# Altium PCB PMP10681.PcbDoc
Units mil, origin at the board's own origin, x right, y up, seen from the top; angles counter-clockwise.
Board outline 3500 x 2650 mil, 4 copper layers (Top Layer, MidLayer1, MidLayer2, Bottom Layer), stack 62.2 mil thick; 65 components, 23 nets, 138 pads, 219 vias.
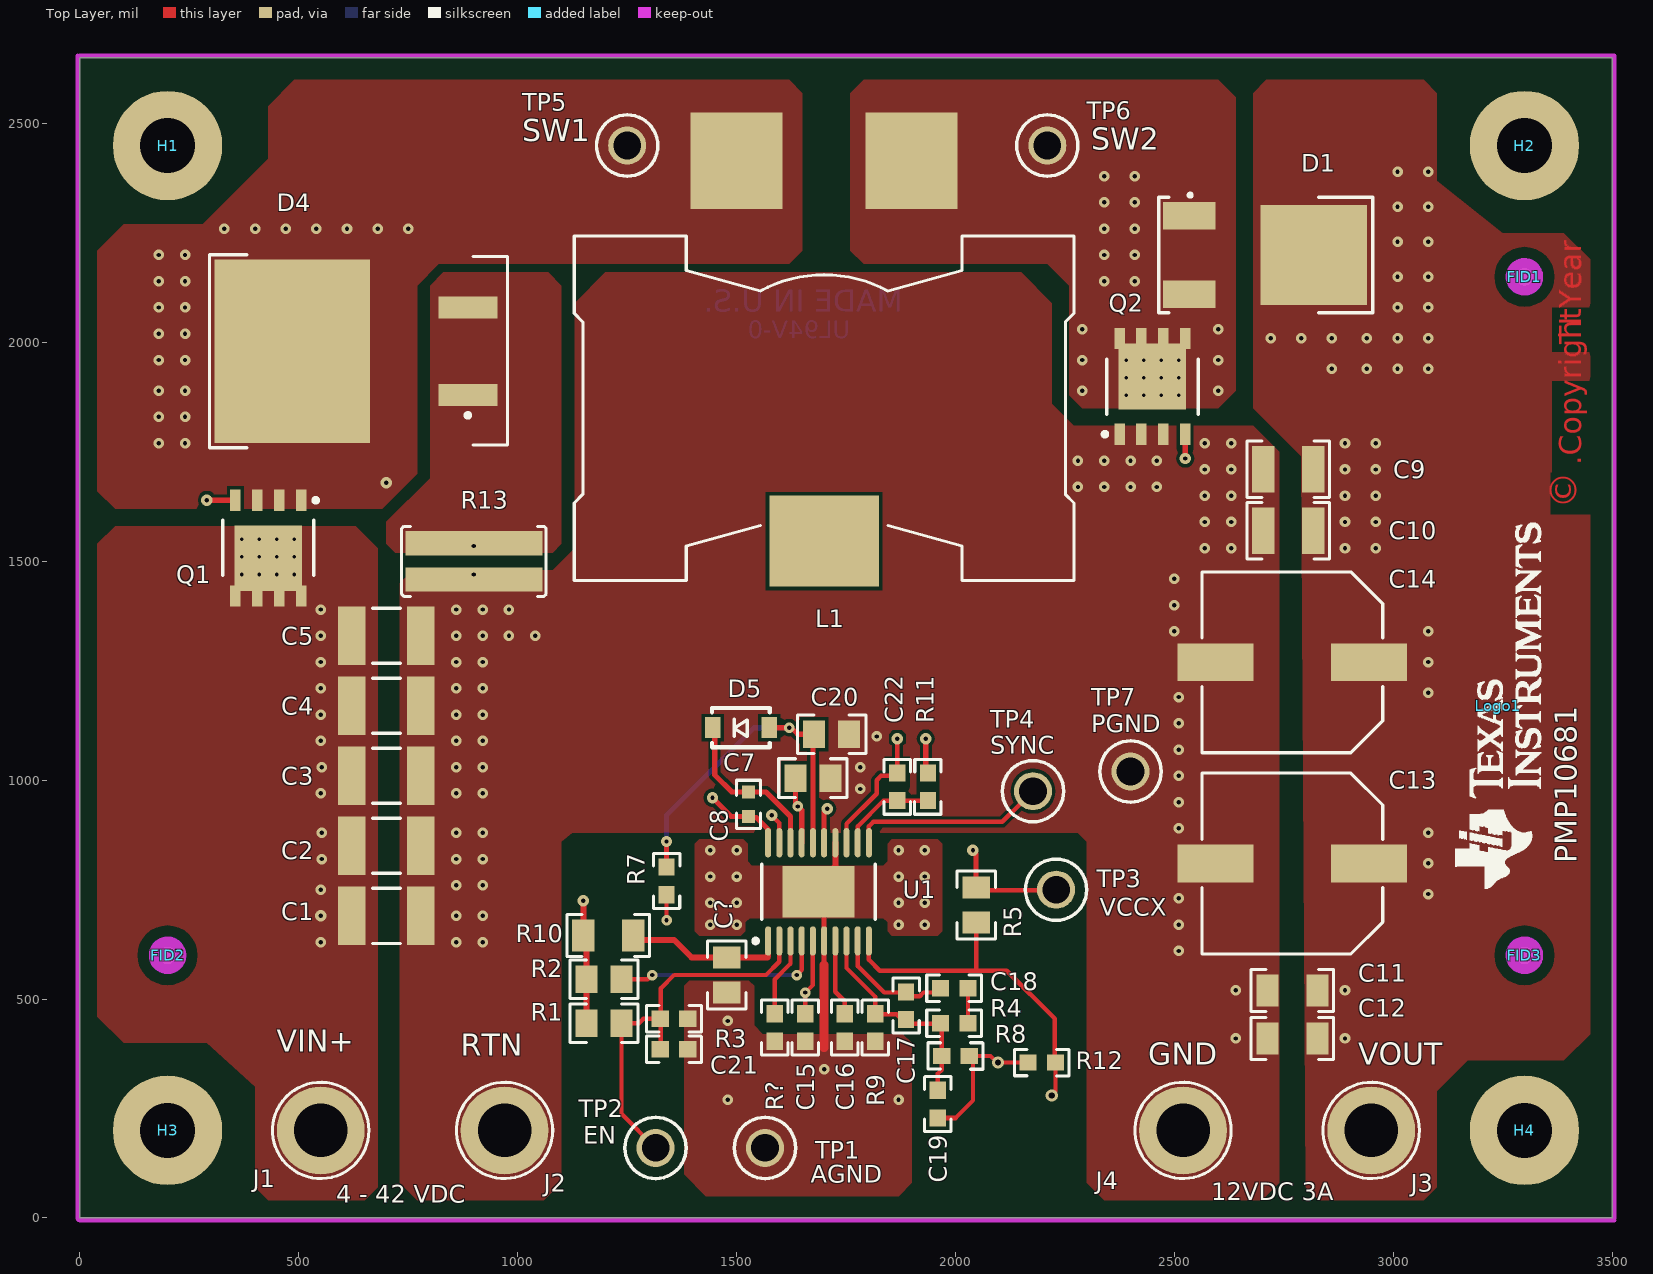
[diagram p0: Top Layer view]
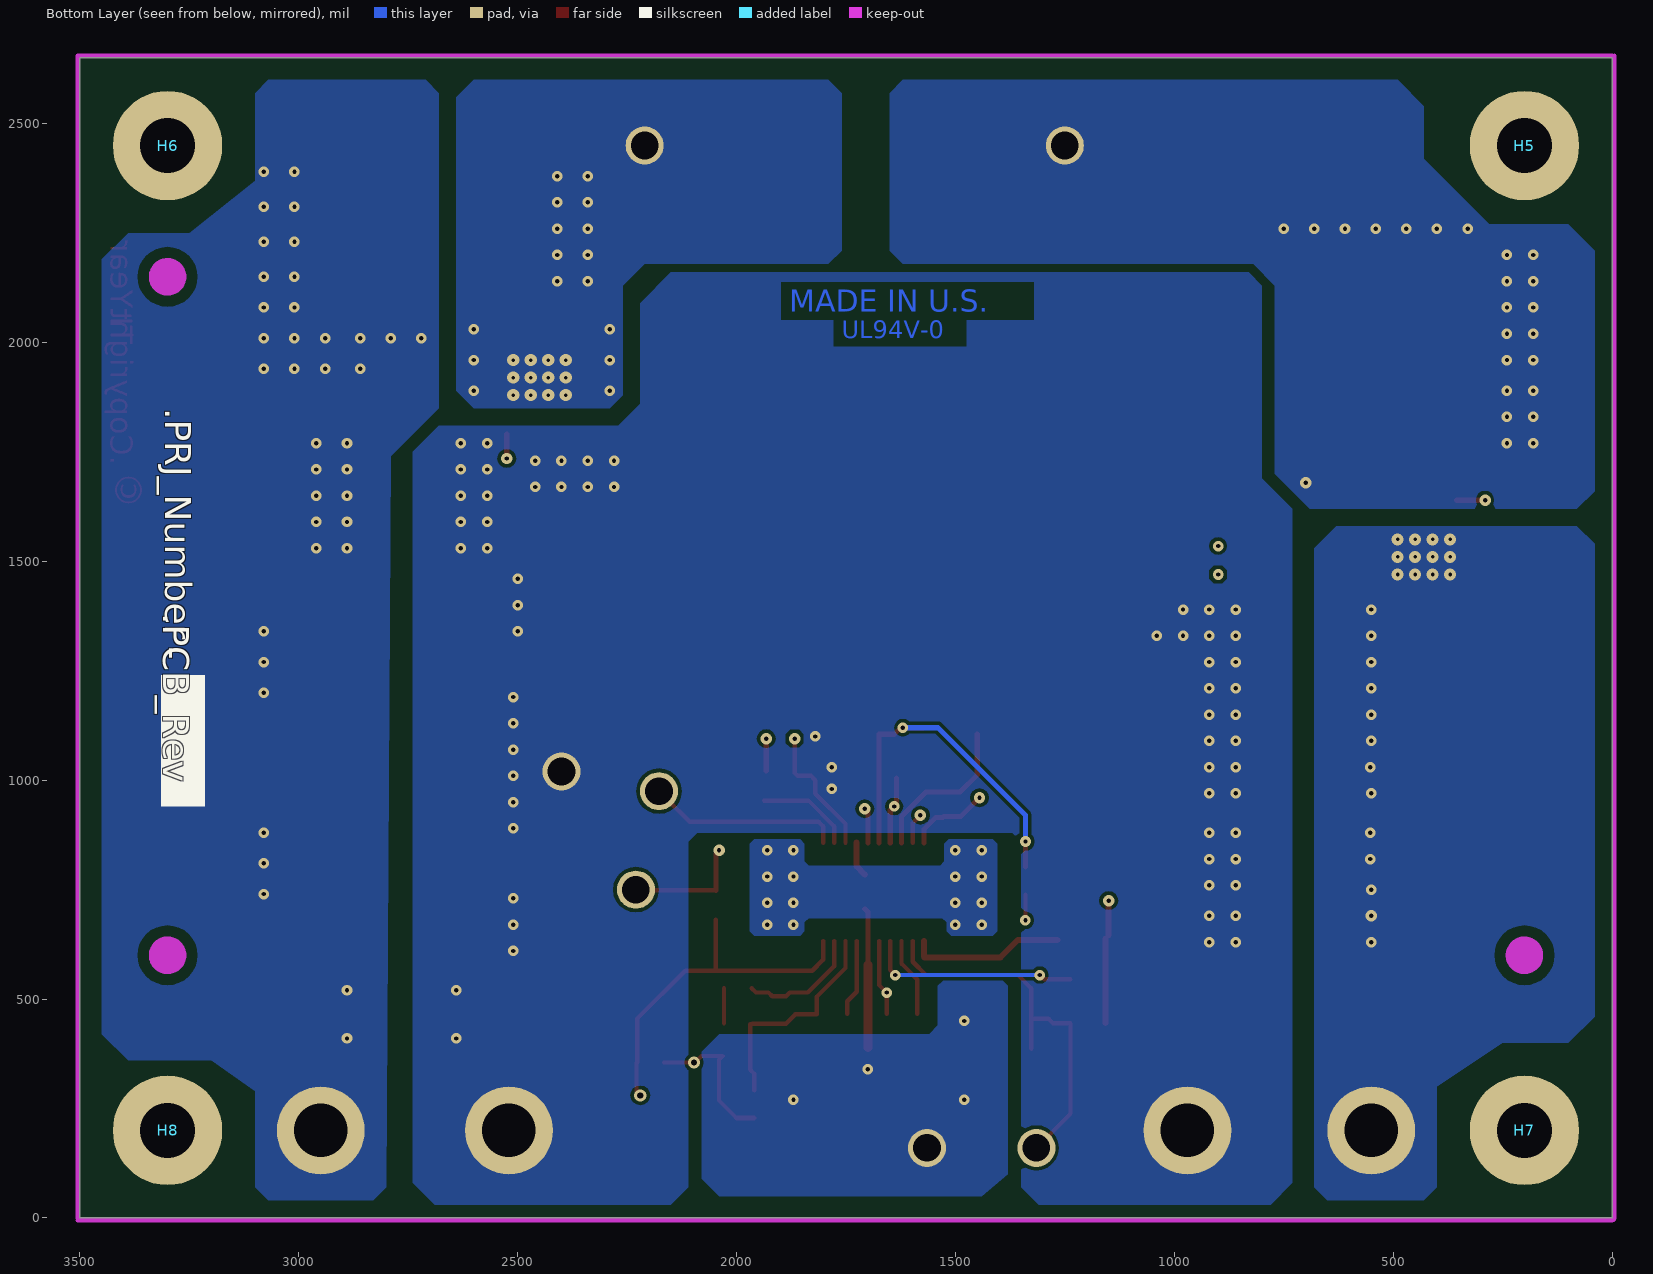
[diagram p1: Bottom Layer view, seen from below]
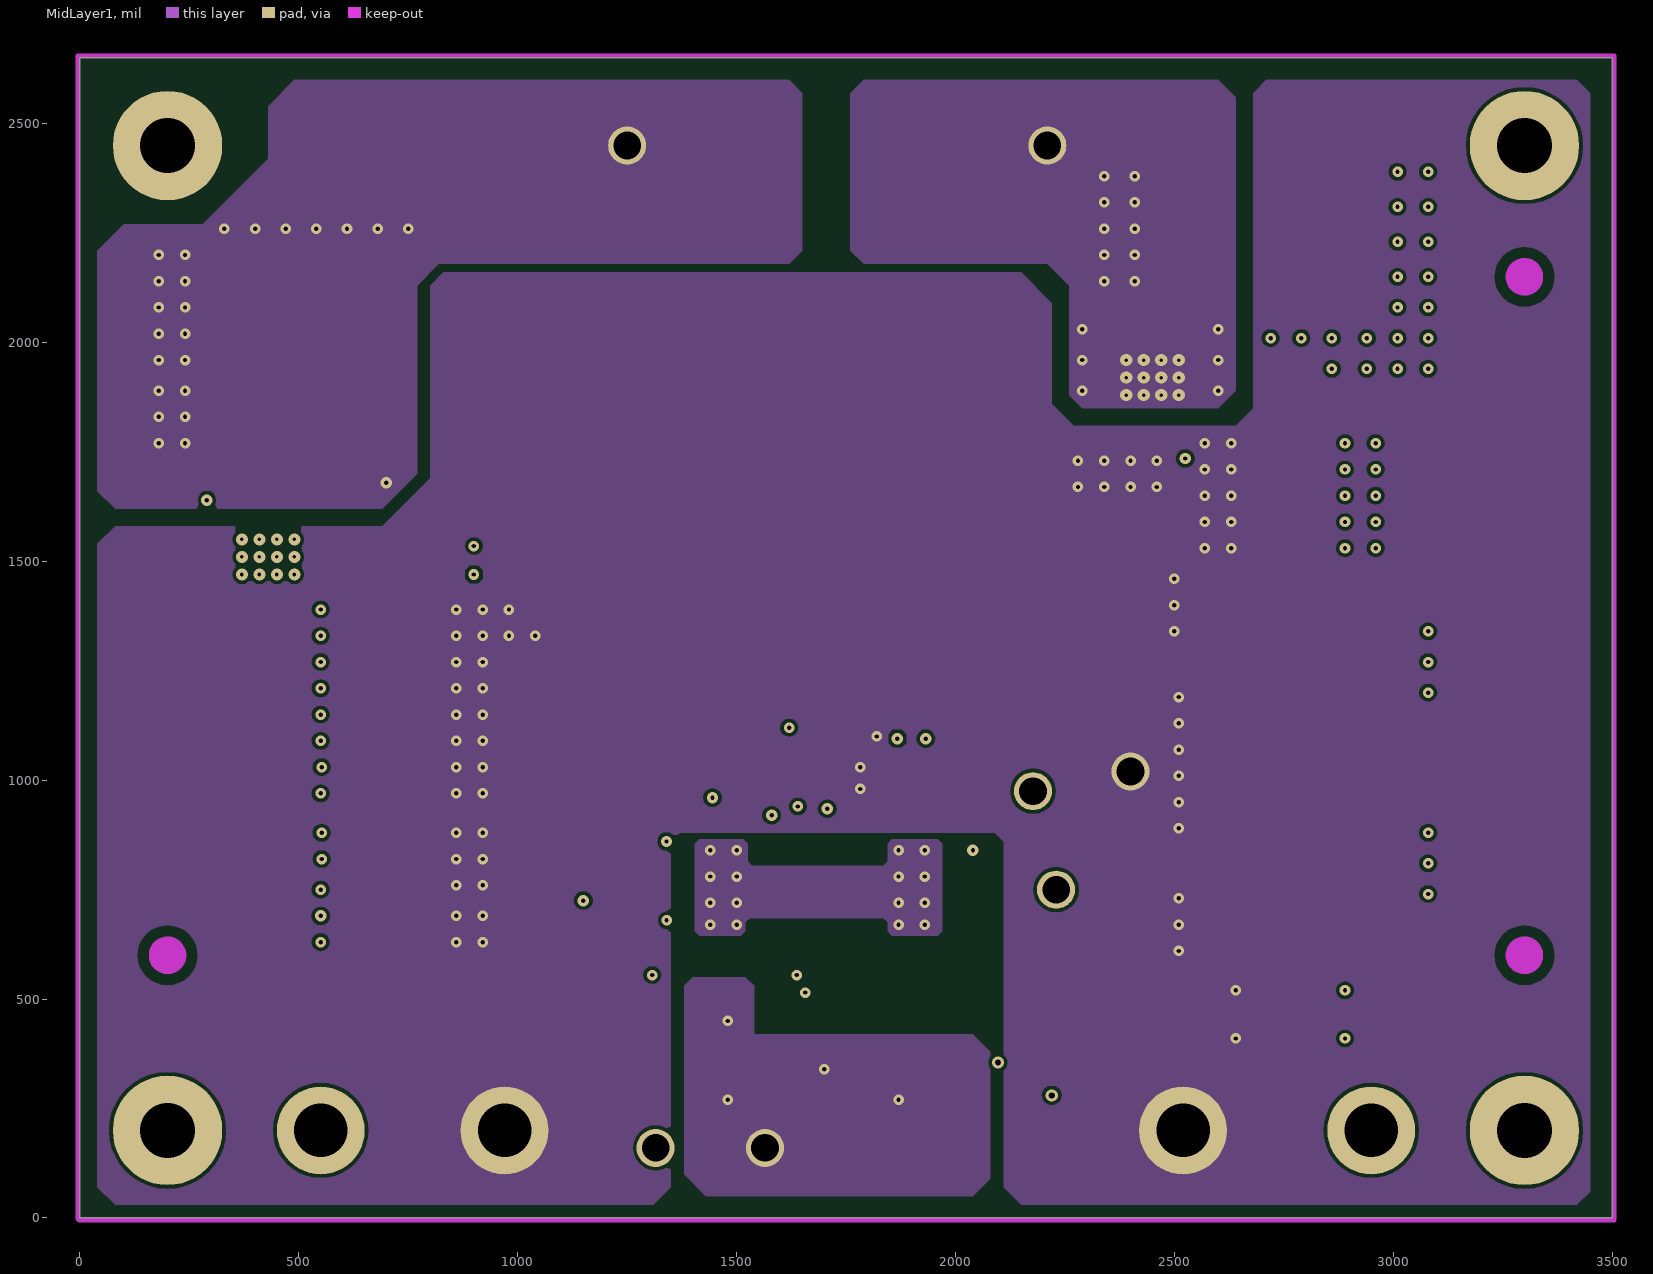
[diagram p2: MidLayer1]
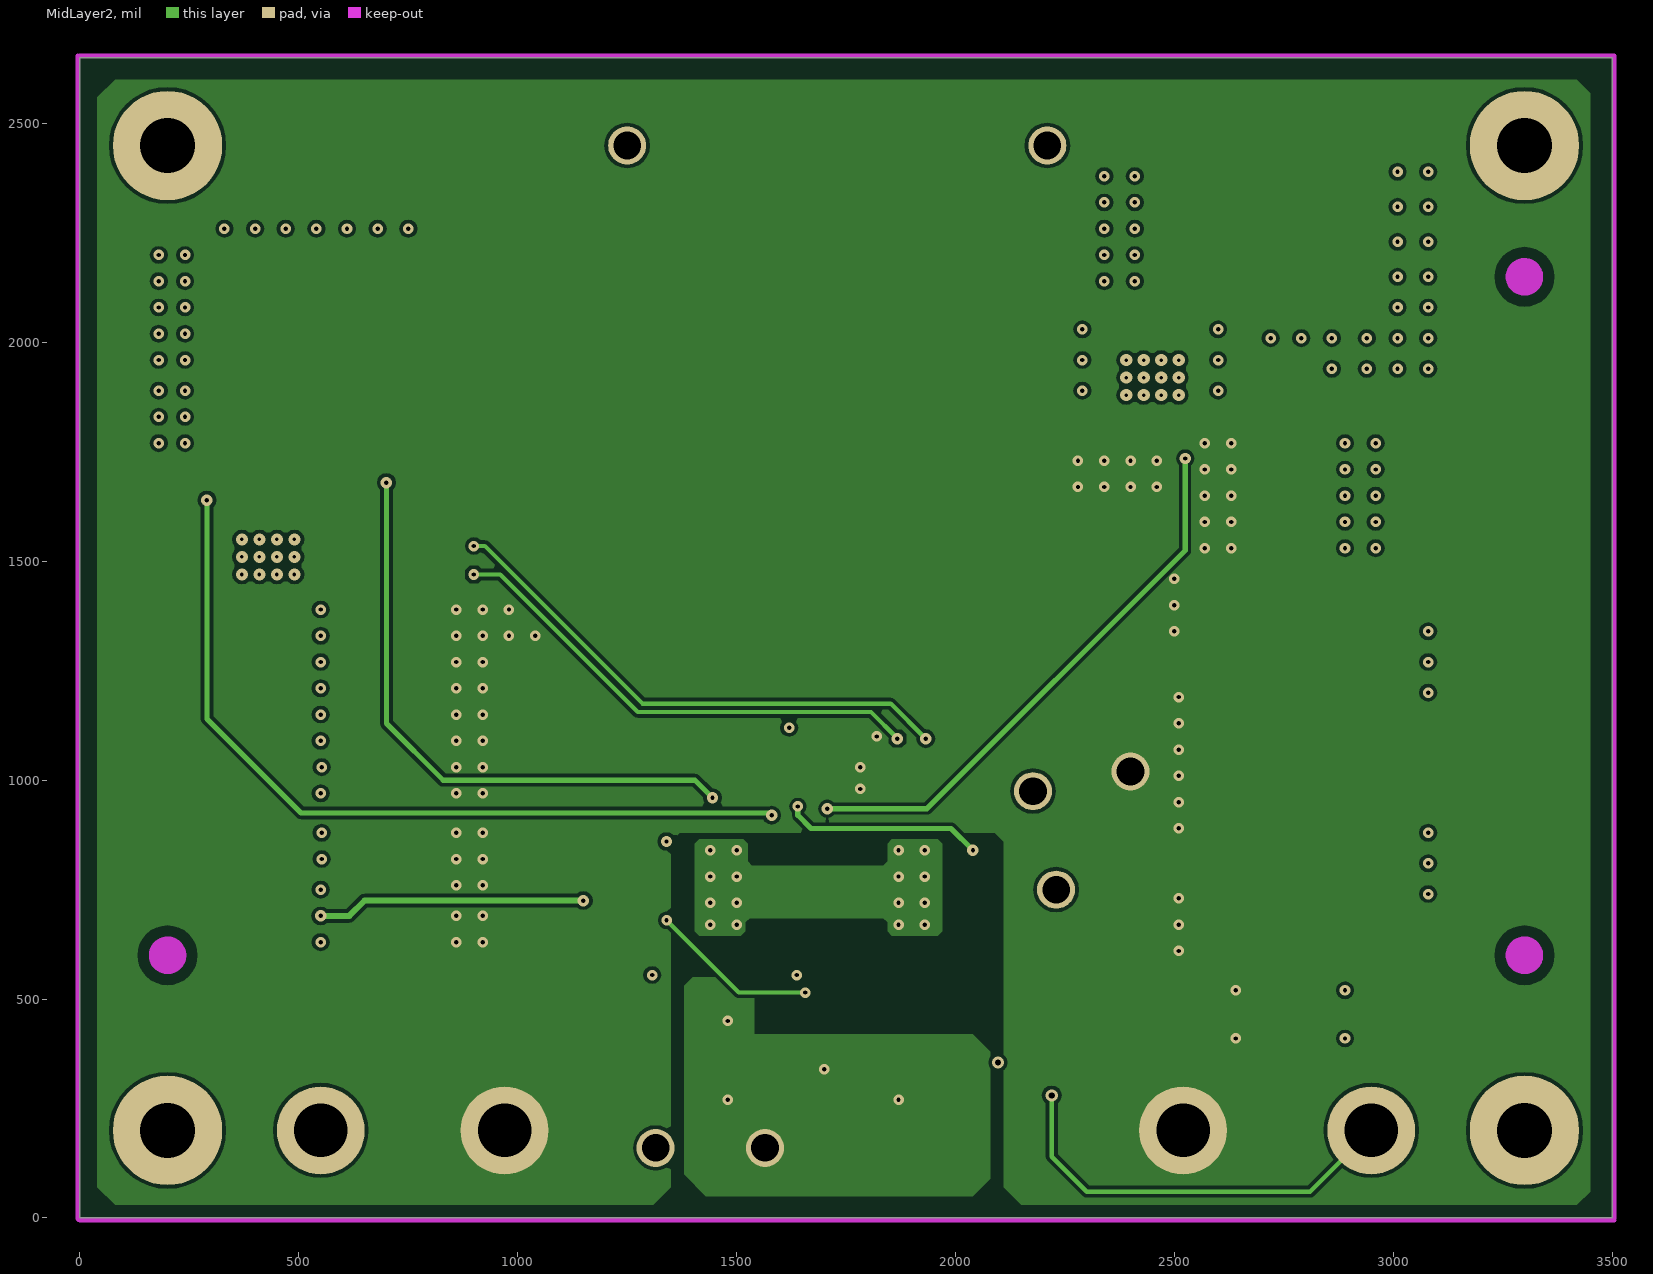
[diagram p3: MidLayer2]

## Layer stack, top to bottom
Top Solder: solder mask 0.4, Solder Resist, Dk 3.5
Top Layer: signal copper 2.8
Dielectric1: core 17, FR-4, Dk 4.8
MidLayer1: signal copper 2.8
Dielectric2: prepreg 17, FR-4, Dk 4.8
MidLayer2: signal copper 2.8
Dielectric3: core 17, FR-4, Dk 4.8
Bottom Layer: signal copper 2.8
Bottom Solder: solder mask 0.4, Solder Resist, Dk 3.5

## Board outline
0,0 3500,0 3500,2650 0,2650

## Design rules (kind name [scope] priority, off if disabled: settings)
AcuteAngle [All] p1: minimum=4.50000000000000E+0001 checktracksonly=FALSE
AssemblyTestPointUsage [All] p1: valid=2
Clearance Clearance_Keepouts [((IsTrack Or IsArc) And Not InPoly) And IsFree and IsKeepOut vs ((IsTrack Or IsArc) And Not InPoly) And IsFree and IsKeepOut] p1: gap=8
Clearance Clearance_BoardEdge_MountingHoles [OnCopper and InComponentClass('Mounting Holes') vs IsKeepOut] p2: gap=40
Clearance Clearance_BoardEdge_Poly [OnCopper and InPoly vs IsKeepOut] p3: gap=25
Clearance Clearance_BoardEdge [OnCopper and Not InComponentClass('Logo') and not InComponentClass('FiducialMark') and not InRegion(1000,500,4000,8000) vs IsKeepOut] p4: gap=40
Clearance [All] p5: gap=8
ComponentClearance ComponentClearance_Logo [InComponentClass(Logo)] p1: gap=10 collisioncheckmode=3 verticalgap=10 showdistances=FALSE
ComponentClearance ComponentClearance_ScrewToNut [(HasFootprint('NY PMS 440 0025 PH')) vs (HasFootprint('Keystone_1902C'))] p2: gap=5 collisioncheckmode=3 verticalgap=10 showdistances=FALSE
ComponentClearance ComponentClearance_MountingHoles [InComponentClass('Mounting Holes')] p3: gap=100 collisioncheckmode=3 verticalgap=100000 showdistances=FALSE
ComponentClearance ComponentClearance_SmallPassives [HasFootprint('0201*') or HasFootprint('0402*') or HasFootprint('0508') or HasFootprint('0603*') or HasFootprint('0612') or HasFootprint('0805*') or HasFootprint('0815*') or HasFootprint('0830*') or HasFootprint('1206*') or HasFootprint('1210*') or HasFootprint('1808*') or HasFootprint('1812*') or HasFootprint('1825*') or HasFootprint('2010*') or HasFootprint('2220*') or HasFootprint('2225*') or HasFootprint('2512*') or HasFootprint('2728*') or HasFootprint('3518*') vs HasFootprint('0201*') or HasFootprint('0402*') or HasFootprint('0508') or HasFootprint('0603*') or HasFootprint('0612') or HasFootprint('0805*') or HasFootprint('0815*') or HasFootprint('0830*') or HasFootprint('1206*') or HasFootprint('1210*') or HasFootprint('1808*') or HasFootprint('1812*') or HasFootprint('1825*') or HasFootprint('2010*') or HasFootprint('2220*') or HasFootprint('2225*') or HasFootprint('2512*') or HasFootprint('2728*') or HasFootprint('3518*')] p4: gap=20 collisioncheckmode=3 verticalgap=10 showdistances=FALSE
ComponentClearance ComponentClearance_THtoSMT [IsThruComponent vs IsSMTComponent] p5: gap=50 collisioncheckmode=3 verticalgap=100000 showdistances=FALSE
ComponentClearance ComponentClearance_THtoTH [IsThruComponent vs IsThruComponent] p6: gap=50 collisioncheckmode=3 verticalgap=100000 showdistances=FALSE
ComponentClearance [All] p7: gap=10 collisioncheckmode=3 verticalgap=10 showdistances=FALSE
DiffPairsRouting [All] p1: maxlimit=100 minlimit=10 mostfreqgap=10 toplayer_minwidth=15 toplayer_maxwidth=15 toplayer_prefwidth=15 midlayer1_minwidth=15 midlayer1_maxwidth=15 midlayer1_prefwidth=15 midlayer2_minwidth=15 midlayer2_maxwidth=15 midlayer2_prefwidth=15 bottomlayer_minwidth=15 bottomlayer_maxwidth=15 bottomlayer_prefwidth=15 maxuncoupledlength=1000
FabricationTestPointUsage TestPointUsage [All] p1: valid=2 allowmultiple=FALSE
FabricationTestpoint Testpoint [All] p1: side=3 testpointundercomponent=TRUE minsize=40 maxsize=100 preferedsize=60 minholesize=0 maxholesize=40 preferedholesize=32 testpointgrid=1 allowsidetop=TRUE allowsidebottom=TRUE usegrid=TRUE gridtolerance=0.01
FanoutControl Fanout_LCC [IsLCC] p1: bgadir=Out bgaviamode=Centered fanoutstyle=Auto fanoutdirection=Alternating viagrid=1 // Fanout_LCC (Default Rule)
FanoutControl Fanout_BGA [IsBGA] p2: bgadir=Out bgaviamode=Centered fanoutstyle=Auto fanoutdirection=Alternating viagrid=1 // Fanout_BGA (Default Rule)
FanoutControl Fanout_Default [All] p4: bgadir=Out bgaviamode=Centered fanoutstyle=Auto fanoutdirection=Alternating viagrid=1 // Fanout_Default (Default Rule)
FanoutControl Fanout_Small [(CompPinCount < 5)] p5: bgadir=Out bgaviamode=Centered fanoutstyle=Auto fanoutdirection=OutThenIn viagrid=1 // Fanout_Small (Default Rule)
HoleSize [All] p1: absolutevalues=TRUE maxlimit=251 minlimit=8 maxpercent=80.000 minpercent=20.000
MinimumAnnularRing [All] p1: minimumring=7
MinimumSolderMaskSliver MinimumSolderMaskSliver_Logo [InComponentClass('Logo') vs InComponentClass('Logo')] p1: minsoldermaskwidth=0.7
MinimumSolderMaskSliver [All] p2: minsoldermaskwidth=4
PlaneClearance PolygonClearance [IsPolygon] p1: clearance=12
PlaneConnect PlaneConnect_1 [All] p1: planeconnectstyle=Relief reliefexpansion=20 reliefentries=4 reliefconductorwidth=10 reliefairgap=10
PlaneConnect [All] p2: planeconnectstyle=Relief reliefexpansion=10 reliefentries=4 reliefconductorwidth=10 reliefairgap=10
PolygonConnect [All] p1: connectstyle=Direct reliefconductorwidth=10 reliefentries=4 polygonreliefangle="90 Angle" airgapwidth=10
RoutingVias [All] p1: holewidth=16 width=34 viastyle="Through Hole" minholewidth=8 minwidth=20 maxholewidth=40 maxwidth=65
SMDToCorner [All] p1: distance=30000
SilkToSilkClearance [All] p1: silktosilkclearance=5
SilkToSolderMaskClearance SilkscreenOverComponentPads [IsPad] p1: minsilkscreentomaskgap=5 clearancetoexposedcopper=TRUE
SolderMaskExpansion [All] p1: expansion=3
UnpouredPolygon [All] p1: allowunpoured=FALSE
Width [All] p1: maxlimit=100 minlimit=6 preferedwidth=10 checkconnectedcopper=TRUE
14 further rules are at their usual default settings.

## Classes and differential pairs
component class "Mounting Holes": H1 H2 H3 H4
component class Logo: Logo1
component class 87060720_HW_TMP: FID1 FID2 FID3 H1 H2 H3 H4 H5 H6 H7 H8 Logo1
component class FiducialMark: FID1 FID2 FID3
component class 870600720_TMP_Sh1: C1 C2 C3 C4 c5 C7 C8 C9 C10 C11 C12 C13 C14 C15 C16 C17 C18 C19 C20 C21 C22 C? D1 D4 D5 J1 J2 J3 J4 L1 Q1 Q2 R1 R2 R3 R4 R5 R7 R8 R9 R10 R11 R12 R13 R? TP1 TP2 TP3 TP4 TP5 TP6 TP7 U1

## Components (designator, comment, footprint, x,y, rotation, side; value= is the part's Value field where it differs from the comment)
C1 "C4532X7R2A225M" 1812 700,690 r0 top (schematic designator C5)
C2 "C4532X7R2A225M" 1812 700,850 r0 top (schematic designator C4)
C3 "C4532X7R2A225M" 1812 700,1010 r0 top
C4 "C4532X7R2A225M" 1812 700,1170 r0 top (schematic designator C2)
C5 "C4532X7R2A225M" 1812 700,1330 r0 top (schematic designator C1)
C7 "GRM219R71E105KA88D" 0805_HV 1674.41,1005 r0 top (schematic designator C20)
C8 "GRM188R72A104KA35D" 0603_HV 1527.2,945 r270 top (schematic designator C6)
C9 "GRM32ER61C476KE15L" 1210 2760,1710 r180 top (schematic designator C10)
C10 "GRM32ER61C476KE15L" 1210 2760,1570 r180 top (schematic designator C9)
C11 "12063C474KAT2A" 1206 2770,520 r180 top
C12 "12063C474KAT2A" 1206 2770,410 r180 top
C13 "APXH160ARA181MJ80G" CAPSMT_62_J80 2770,810 r180 top (schematic designator C7)
C14 "APXH160ARA181MJ80G" CAPSMT_62_J80 2770,1270 r180 top (schematic designator C8)
C15 "GRM1885C2A331JA01D" 0603 1657.2,435 r270 top (schematic designator C18)
C16 "GRM188R72A104KA35D" 0603 1747.2,435 r270 top (schematic designator C17)
C17 "GRM188R72A222KA01D" 0603 1887.2,485 r90 top (schematic designator C15)
C18 "C1608X7R2A472K" 0603 1997.2,525 r180 top (schematic designator C22)
C19 "Used in BOM report" 0603 1960,260 r90 top
C20 "GRM219R71E105KA88D" 0805_HV 1717.2,1105 r0 top (schematic designator C21)
C21 "GRM188R72A104KA35D" 0603 1357.2,385 r0 top (schematic designator C16)
C22 "Used in BOM report" 0603 1867.2,985 r90 top (schematic designator C14)
C? "C0805C104K1RACTU" 0805_HV 1477.2,555 r90 top
D1 "MBRD1035CTLT4G" DPAK 2730,2200 r0 top (schematic designator D2)
D4 "VB40100C-E3/4W" DDPAK 640,1980 r180 top (schematic designator D3)
D5 "BAT41ZFILM" SOD-123 1510,1120 r0 top
FID1 "Fiducial" Fiducial10-20 3300,2150 r0 top
FID2 "Fiducial" Fiducial10-20 200,600 r0 top
FID3 "Fiducial" Fiducial10-20 3300,600 r0 top
H1 "NY PMS 440 0025 PH" "NY PMS 440 0025 PH" 200,2450 r0 top locked
H2 "NY PMS 440 0025 PH" "NY PMS 440 0025 PH" 3300,2450 r0 top locked
H3 "NY PMS 440 0025 PH" "NY PMS 440 0025 PH" 200,200 r0 top locked
H4 "NY PMS 440 0025 PH" "NY PMS 440 0025 PH" 3300,200 r0 top locked
H5 "1902C" Keystone_1902C 200,2450 r180 bottom locked
H6 "1902C" Keystone_1902C 3300,2450 r180 bottom locked
H7 "1902C" Keystone_1902C 200,200 r180 bottom locked
H8 "1902C" Keystone_1902C 3300,200 r180 bottom locked
J1 "Suggest using a net name here" Keystone1503-2 550,200 r0 top
J2 "Suggest using a net name here" Keystone1503-2 970,200 r0 top
J3 "Suggest using a net name here" Keystone1503-2 2950,200 r0 top
J4 "Suggest using a net name here" Keystone1503-2 2520,200 r0 top
L1 "SER2915H-103KL" SER2915 1700,1850 r270 top
Logo1 "Texas Instruments" TI_Stacked_Overlay_Small 3240,1170 r90 top
Q1 "SI7148DP" PowerPAK_SO-8 430,1530 r270 top
Q2 "SI7148DP" PowerPAK_SO-8 2450,1900 r90 top
R1 "CRCW080575K0FKEA" 0805_HV 1197.2,445 r180 top (schematic designator R2)
R2 "CRCW08051M00FKEA" 0805_HV 1197.2,545 r180 top (schematic designator R3)
R3 "RT0603BRD0729K4L" 0603 1357.2,455 r180 top (schematic designator R11)
R4 "CRCW060310K0FKEA" 0603 1997.2,445 r180 top (schematic designator R10)
R5 "CRCW08050000Z0EA" 0805_HV 2047.2,715 r270 top (schematic designator R1)
R7 "Used in BOM report" 0603 1340,770 r90 top
R8 "CRCW06032K67FKEA" 0603 2000,370 r0 top
R9 "CRCW0603309RFKEA" 0603 1817.2,435 r90 top (schematic designator R14)
R10 "CRCW12060000Z0EA" 1206 1207.2,645 r180 top (schematic designator R4)
R11 "CRCW06030000Z0EA" 0603 1937.2,985 r90 top (schematic designator R5)
R12 "CRCW060310R0FKEA" 0603 2197.2,355 r0 top (schematic designator R9)
R13 "RL7520WT-R015-G" "3008M - Silk" 900,1500 r270 top (schematic designator R6)
R? "CRCW060316K2FKEA" 0603 1587.2,435 r90 top
TP1 "AGND" Keystone5011 1565,160 r0 top (schematic designator TP9)
TP2 "EN" Keystone5012 1315,160 r0 top (schematic designator TP7)
TP3 "VCCX" Keystone5010 2230,750 r0 top (schematic designator TP2)
TP4 "SYNC" Keystone5012 2177.2,975 r0 top (schematic designator TP8)
TP5 "SW1" Keystone5127 1250,2450 r0 top (schematic designator TP3)
TP6 "SW2" Keystone5013 2210,2450 r0 top (schematic designator TP4)
TP7 "PGND" Keystone5011 2400,1020 r0 top
U1 "LM25118MH/NOPB" MXA20A_N_NoVias 1687.2,745 r90 top

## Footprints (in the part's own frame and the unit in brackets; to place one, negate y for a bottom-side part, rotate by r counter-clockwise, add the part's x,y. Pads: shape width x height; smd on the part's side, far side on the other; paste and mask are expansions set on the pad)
0603 [mm] "0603 from SM-752 data"
  rect 1x0.95 smd: 1(-0.8,0) 2(0.8,0)
  silkscreen extent -1.59,-0.77 1.59,0.77, body extent -0.87,-0.47 0.87,0.47, height 0.85
0603_HV [mil] "Ernesto recommended land pattern.  26 mil between pads."
  rect 30x30 smd: 1(-28,0) 2(28,0)
  silkscreen extent -55,-27 55,27, body extent -34,-19 34,19, height 33
0805_HV [mil] "0805 with 30mil clearance between pads"
  rect 50x63 smd: 1(-40,0) 2(40,0)
  silkscreen extent -78,-44 78,44, body extent -43,-29 43,29, height 43
1206 [mm] "1206 from SM-752 data"
  rect 1.3x1.85 smd: 1(-1.45,0) 2(1.45,0)
  silkscreen extent -2.39,-1.22 2.39,1.22, body extent -1.7,-0.9 1.7,0.9, height 1.35
1210 [mm] "1210 from SM-752 data"
  rect 1.3x2.7 smd: 1(-1.45,0) 2(1.45,0)
  silkscreen extent -2.39,-1.64 2.39,1.64, body extent -1.7,-1.35 1.7,1.35, height 1.35
1812 [mm]
  rect 1.6x3.4 smd: 1(-2,0) 2(2,0)
  silkscreen extent -0.8,-1.6 0.8,1.6, body extent -2.4,-1.7 2.4,1.7, height 1.35
"3008M - Silk" [mm] "Chip Resistor, 2-Leads, Body 2.0x7.5mm, IPC Low Density based on Susumu RL7520W dimensions."
  rect 1.4x7.95 smd: 1(-1.05,0) 2(1.05,0)
  silkscreen extent -2.03,-4.19 2.03,4.19, body extent -1.1,-3.9 1.1,3.9, height 0.6
CAPSMT_62_J80 [mm] "10 x 7.7mm:  Chemi-Con J80"
  rect 4.4x2.2 smd: 1(-4.438,0.012) 2(4.462,0.012)
  silkscreen extent -5.24,-5.24 5.26,5.26, body extent -5.25,-5.25 5.27,5.27, height 8
DDPAK [mil] "D2-PAK, 3-Pads, Body 9.7x10.4mm (max), IPC Medium Density, using Vishay Silionix recommended pad sizes"
  rect 135x49.49 smd: 1(-246.06,100) 3(-246.06,-100)
  rect 355x420 smd: 4(155.51,0)
  silkscreen extent -337,-220 344,220, body extent -116,-205 264,205, height 190
DPAK [mm] "D-PAK, 3-Pads, Body 6.2x6.7mm (max), IPC Medium Density_modified 2008-05-02 to match OnSemi land pattern"
  rect 3.05x1.6 smd: 1(-4.97,2.28) 3(-4.97,-2.28)
  rect 6.2x5.8 smd: 4(2.25,0)
  silkscreen extent -6.75,-3.35 5.68,3.55, body extent -2.1,-3.35 4.1,3.35, height 2.39
Fiducial10-20 [mm]
  round 1 smd paste-0.5 mask+0.5: 1(0,0)
  Keep-Out Layer circle w1.178: c0,0 r0.5
Keystone1503-2 [mm] "Double Turret"
  round 5.1 hole 3.1: 1(0,0)
  silkscreen extent -2.79,-2.79 2.79,2.79, body extent -2.41,-2.41 2.41,2.41, height 9.2
Keystone5010 [mil] "Keystone Multipurpose loops"
  round 87 hole 63: 1(0,0)
  silkscreen extent -70,-70 70,70, body extent -63,-63 63,62, height 319
Keystone5011 [mil] "Keystone Multipurpose loops"
  round 87 hole 63: 1(0,0)
  silkscreen extent -70,-70 70,70, body extent -63,-63 63,62, height 319
Keystone5012 [mil] "Keystone Multipurpose loops"
  round 87 hole 63: 1(0,0)
  silkscreen extent -70,-70 70,70, body extent -63,-63 63,62, height 319
Keystone5013 [mil] "Keystone Multipurpose loops"
  round 87 hole 63: 1(0,0)
  silkscreen extent -70,-70 70,70, body extent -63,-63 63,62, height 319
Keystone5127 [mil] "Keystone Multipurpose loops"
  round 87 hole 63: 1(0,0)
  silkscreen extent -70,-70 70,70, body extent -63,-63 63,62, height 319
Keystone_1902C [mil] "Hex Standoff, 4-40 threaded, nylon"
  body extent -145,-126 146,126, height 501
MXA20A_N_NoVias [mm] "TSOP, 20-Leads, Body 6.5x4.4mm, Pitch 0.65mm, Exposed Pad, IPC Medium Density"
  oval 1.7x0.35 smd: 1(-2.85,2.925) 2(-2.85,2.275) 3(-2.85,1.625) 4(-2.85,0.975) 5(-2.85,0.325) 6(-2.85,-0.325) 7(-2.85,-0.975) 8(-2.85,-1.625) 9(-2.85,-2.275) 10(-2.85,-2.925) 11(2.85,-2.925) 12(2.85,-2.275) 13(2.85,-1.625) 14(2.85,-0.975) 15(2.85,-0.325) 16(2.85,0.325) 17(2.85,0.975) 18(2.85,1.625) 19(2.85,2.275) 20(2.85,2.925)
  rect 3x4.2 smd: 21(0,0)
  silkscreen extent -2.97,-3.3 1.6,3.77, body extent -2.25,-3.3 2.25,3.3, height 1.1
"NY PMS 440 0025 PH" [mm] "4-40 nylon screw and mounting hole"
  round 6.35 hole 3.2: 1(0,0)
  body extent -3.3,-3.3 3.3,3.3, height 2.69
PowerPAK_SO-8 [mil] "Vishay PowerPAK SO-8, Body 5.3x6.0mm (max), Pitch 1.27mm, IPC Medium Density"
  rect 50x24 smd mask+2.99: 1(-109.5,75) 2(-109.5,25) 3(-109.5,-25) 4(-109.5,-75)
  rect 48x24 smd mask+2.99: 5(109.5,-75) 8(109.5,75)
  rect 48x24 smd paste-12 mask+2.99: 6(109.5,-25) 7(109.5,25)
  rect 150x154 smd paste-75 mask+2.99: 9(22.5,0)
  silkscreen extent -114,-104 62,113, body extent -121,-102 121,102, height 43
SER2915 [mm] "Coilcraft recommended land pattern.  Document 644-2, rev 12/12/08"
  rect 5.59x5.33 smd: 1(-14.355,5.075) 2(-14.355,-5.075)
  rect 5.28x6.35 smd: 3(7.72,0)
  silkscreen extent -10,-14.5 10,14.5, body extent -16.8,-13.95 11.03,13.95, height 15.36
SOD-123 [mm] "On Semi recommended land pattern"
  rect 0.915x1.22 smd: 1(-1.637,0) 2(1.637,0)
  silkscreen extent -1.68,-1.14 1.68,1.14, body extent -1.42,-0.9 1.42,0.9, height 1.35
TI_Stacked_Overlay_Small [mil]
  silkscreen extent -418,-98 418,98

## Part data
C1 C2 C3 C4 C5: "CAP, CERM, 2.2uF, 100V, +/-20%, X7R, 1812"
C7 C20: "CAP, CERM, 1uF, 25V, +/-10%, X7R, 0805"
C8 C16 C21: "CAP, CERM, 0.1uF, 100V, +/-10%, X7R, 0603"
C9 C10: "CAP, CERM, 47uF, 16V, +/-10%, X5R, 1210"
C11 C12: "CAP, CERM, 0.47uF, 25V, +/-10%, X7R, 1206"
C13 C14: "CAP, AL, 180uF, 16V, +/-20%, 0.026 ohm, SMD"
C15: library part GRM188R71H221KA01D, "CAP, CERM, 220 pF, 50 V, +/- 10%, X7R, 0603"
C17: library part GRM188R71H122KA01D, "CAP, CERM, 1200 pF, 50 V, +/- 10%, X7R, 0603"
C18: library part GRM188R71E393KA01D, "CAP, CERM, 0.039 µF, 25 V, +/- 10%, X7R, 0603"
C19 C22: library part Capacitor, "CAP, CERM, xxxF, xxV, [Dielectric], xx%, [Package]"
C?: "CAP, CERM, 0.1uF, 100V, +/-10%, X7R, 0805"
D1: "Diode, Schottky, 35V, 10A, DPAK"
D4: library part MBRB20100CTT4G, "Diode, Schottky, 100V, 20A, DDPAK"
D5: "Diode, Schottky, 100V, 0.2A, SOD-123"
FID1 FID2 FID3: "Fiducial mark.  There is nothing to buy or mount."
H1 H2 H3 H4: "Machine Screw, Round, #4-40 x 1/4, Nylon, Philips panhead"
H5 H6 H7 H8: "Standoff, Hex, 0.5\"L #4-40 Nylon"
J1 J2 J3 J4: library part 1503-2, "Terminal, Turret, TH, Double"
L1: library part 7443630700, "Inductor, Shielded Drum Core, Mn-Zn, 7 µH, 21 A, 0.005608 ohm, SMD"
Logo1: library part TI_Logo, "Texas Instrument Corporate Signature"
Q1 Q2: "MOSFET, N-CH, 75V, 12A, PowerPAK SO-8"
R1: "RES, 75.0k ohm, 1%, 0.125W, 0805"
R2: "RES, 1.00Meg ohm, 1%, 0.125W, 0805"
R3: library part RC0603FR-0764K9L, "RES, 64.9 k, 1%, 0.1 W, 0603"
R4: library part CRCW060313K0FKEA, "RES, 13.0 k, 1%, 0.1 W, 0603"
R5: "RES, 0 ohm, 5%, 0.125W, 0805"
R7: library part Resistor, "RES, xxx ohm, x%, xW, [PackageReference]"
R8: library part RC0603FR-075K6L, "RES, 5.60 k, 1%, 0.1 W, 0603"
R9: library part RC0603FR-071K8L, "RES, 1.80 k, 1%, 0.1 W, 0603"
R10: "RES, 0 ohm, 5%, 0.25W, 1206"
R11: "RES, 0 ohm, 5%, 0.1W, 0603"
R12: "RES, 10.0 ohm, 1%, 0.1W, 0603"
R13: library part RL7520WT-R020-F, "RES, 0.015 ohm, 1%, 2W, 3008"
R?: library part CRCW060322K1FKEA, "RES, 22.1 k, 1%, 0.1 W, 0603"
TP1 TP7: library part 5011, "Test Point, TH, Multipurpose, Black"
TP2 TP4: library part 5012, "Test Point, TH, Multipurpose, White"
TP3: library part 5010, "Test Point, TH, Multipurpose, Red"
TP5: library part 5127, "Test Point, TH, Multipurpose, Blue"
TP6: library part 5013, "Test Point, TH, Multipurpose, Orange"
U1: library part LM5118MH/NOPB, "Wide Voltage Range Buck-Boost Controller, 20-pin TSSOP-EP, Pb-Free"

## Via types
v1: diameter 24, hole 10, Top Layer to Bottom Layer, 181 vias
v2: diameter 28, hole 8, Top Layer to Bottom Layer, tented top, 24 vias
v3: diameter 26, hole 10, Top Layer to Bottom Layer, 12 vias
v4: diameter 28, hole 14, Top Layer to Bottom Layer, 2 vias

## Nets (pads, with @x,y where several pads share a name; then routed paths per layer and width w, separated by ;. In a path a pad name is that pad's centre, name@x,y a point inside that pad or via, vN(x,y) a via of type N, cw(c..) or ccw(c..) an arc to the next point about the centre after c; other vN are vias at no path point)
NetC1_1: C1.1 C2.1 C3.1 C4.1 C5.1 J1.1 Q1.5 Q1.6 Q1.7 Q1.8 Q1.9 R1.2 R2.2 R10.2 | length 887.5
  Top Layer w14: v3(1150,725) 1150.12,724.88 R10.2 ; R1.2 R2.2 R10.2@1157.2,637.91
  MidLayer2 w14: v3(550,690) 615,690 650,725 v3(1150,725)
  other v1: 550,630 550,750 551.97,820 551.97,880 550,970 551.97,1030 550,1090 550,1150 550,1210 550,1270 550,1330 550,1390
  other v2: 370,1470 410,1470 450,1470 490,1470 370,1510 410,1510 450,1510 490,1510 370,1550 410,1550 450,1550 490,1550
NetC8_1: C8.1 D5.1 U1.18 | length 365.1
  Top Layer w12: D5.1@1450,1105 1450,1012.2 1489.2,973 C8.1 1567,973 1623.23,916.77 U1.18
NetC8_2: C8.2 D4.4 L1.2 Q1.1 Q1.2 Q1.3 TP5.1 U1.20 | length 1553.1
  Top Layer w12: v3(1445,960) 1488,917 C8.2 1529.2,915 1545,915 1572.05,887.95 U1.20
  MidLayer2 w12: v3(700,1680) 700,1130 830,1000 1405,1000 v3(1445,960)
  other v1: 180,1770 240,1770 180,1830 240,1830 180,1890 240,1890 180,1960 240,1960 180,2020 240,2020 180,2080 240,2080 180,2140 240,2140 180,2200 240,2200 330,2260 400,2260 470,2260 540,2260 610,2260 680,2260 750,2260
NetC9_1: C9.1 C10.1 C11.1 C12.1 C13.1 C14.1 D1.4 J3.1 R5.2 R12.2 U1.10 | length 1779.9
  Top Layer w10: U1.10 1802.36,589.84 1827.2,565 2047.2,565 ; R5.2@2047.2,681.54 2047.2,565 ; v4(2220,280) 2228.7,288.7 R12.2 ; R12.2@2227.2,355 2227.2,455 2117.2,565 2047.2,565
  MidLayer2 w10: v4(2220,280) 2220,140 2300,60 2810,60 J3.1
  other v1: 2890,410 2890,520 3080,740 3080,810 3080,880 3080,1200 3080,1270 3080,1340 2890,1530 2960,1530 2890,1590 2960,1590 2890,1650 2960,1650 2890,1710 2960,1710 2890,1770 2960,1770 2860,1940 2940,1940 3010,1940 3080,1940 2720,2010 2790,2010 2860,2010 2940,2010 3010,2010 3080,2010 3010,2080 3080,2080 3010,2150 3080,2150 3010,2230 3080,2230 3010,2310 3080,2310 3010,2390 3080,2390
NetC15_1: C15.1 R7.1 U1.5 | length 617.5
  Top Layer w10: v1(1340,680) R7.1 ; C15.1 v1(1657.2,515) 1674.41,532.2 U1.5
  MidLayer2 w10: v1(1340,680) 1505,515 v1(1657.2,515)
NetC16_1: C16.1 U1.7 | length 175.3
  Top Layer w10: U1.7 1725.59,516.61 1747.2,495 C16.1
NetC17_1: C17.1 C19.2 R4.2 R8.1 R9.2 U1.8 | length 505.3
  Top Layer w10: U1.8 1751.18,571.02 1817.2,505 1817.2,465 1865.71,465 1887.2,443.5 R4.2@1964.21,443.5 ; C19.2 1960,330 1968.5,338.5 R8.1 R4.2@1968.5,442.2
NetC17_2: C17.2 C18.2 U1.9 | length 282.5
  Top Layer w10: U1.9 1776.77,575.43 1837.2,515 1878.7,515 1887.2,506.5 1918.7,506.5 1927.2,515 1955.71,515 C18.2
NetC18_1: C18.1 R4.1 | length 80
  Top Layer w10: R4.1 C18.1
NetC19_1: C19.1 R8.2 R12.1 | length 342
  Top Layer w10: 2000,228.5 2040,268.5 2040,361.5 R8.2 2080,370 2095,355 v4(2097.2,355) R12.1
  Top Layer w12: C19.1 2000,228.5
NetC21_1: C21.1 R1.1 R3.2 TP2.1 U1.2 | length 891.2
  Top Layer w10: TP2.1 1237.2,237.8 R1.1 1277.2,445 1287.2,455 R3.2 ; C21.1@1327.2,386.5 1327.2,525 1357.2,555 1567.2,555 1597.64,585.43 U1.2
NetC22_1: C22.1 R11.1 U1.12 | length 222.2
  Top Layer w10: U1.12 1776.77,894.57 1835.71,953.5 C22.1 R11.1
NetC?_2: C?.2 R10.1 U1.1 | length 358
  Top Layer w14: R10.1@1267.2,635 1357.2,635 1397.2,595 C?.2 1570,595 1572.05,597.05 U1.1
NetD1_1: D1.1 D1.3 L1.1 Q2.5 Q2.6 Q2.7 Q2.8 Q2.9 TP6.1
  other v1: 2290,1890 2600,1890 2290,1960 2600,1960 2290,2030 2600,2030 2340,2140 2410,2140 2340,2200 2410,2200 2340,2260 2410,2260 2340,2320 2410,2320 2340,2380 2410,2380
  other v2: 2390,1880 2430,1880 2470,1880 2510,1880 2390,1920 2430,1920 2470,1920 2510,1920 2390,1960 2430,1960 2470,1960 2510,1960
NetD4_1: D4.1 D4.3 R11.2 R13.1 | length 1288
  Top Layer w12: R11.2@1932.2,1021.5 v3(1932.2,1095)
  MidLayer2 w10: v1(900,1535) 925,1535 1285,1175 1852.2,1175 v3(1932.2,1095)
NetQ1_4: Q1.4 U1.19 | length 2017.9
  Top Layer w10: v3(1580,920) 1597.64,902.36 U1.19
  Top Layer w12: v3@290.5,1639.5 Q1.4 ; v3(1580,920) v3@1582.2,920
  MidLayer2 w10: v3@1575,925 v3(1580,920)
  MidLayer2 w12: v3(290,1640) 290,1140 505,925 v3@1575,925
NetQ2_4: Q2.4 U1.15 | length 1415.5
  Top Layer w12: U1.15 1700,927.8 v3(1707.2,935) ; v3(2525,1735) v3@2525,1745 ; Q2.4 v3@2525,1745 ; v3@2530,1740 v3@2525,1745
  MidLayer2 w12: v3(1707.2,935) 1935,935 2525,1525 v3(2525,1735)
NetR2_1: R2.1 U1.4 | length 472.6
  Top Layer w10: R2.1 1297.2,545 ; v1(1637.2,555) 1648.82,566.61 U1.4
  Bottom Layer w10: v1(1307.2,555) v1(1637.2,555)
NetR?_2: R?.2 U1.3 | length 181.2
  Top Layer w10: R?.2 1587.2,545 1623.23,581.02 U1.3
NetTP4_1: TP4.1 U1.11 | length 417.3
  Top Layer w10: U1.11 1802.36,894.7 1812.66,905 2107.2,905 TP4.1@2157.2,955
SGND: C1.2 C2.2 C3.2 C4.2 C5.2 C7.2 C9.2 C10.2 C11.2 C12.2 C13.2 C14.2 C15.2 C16.2 C20.2 C21.2 C22.2 C?.1 J2.1 J4.1 Q2.1 Q2.2 Q2.3 R3.1 R9.1 R13.2 R?.1 TP1.1 TP7.1 U1.6 U1.13 U1.14 U1.21 | length 1827.7
  Top Layer w10: U1.13 1751.18,900.47 1820,969.29 1820,1000 1830,1010 1860.71,1010 C22.2 v3(1867.2,1095)
  Top Layer w12: 1700,577.8 U1.6 1700,698.74 U1.21@1706.89,705.63
  Top Layer w14: 1700,389.01 1700.5,388.5 ; U1.21@1706.89,784.37 1725.59,803.07 U1.14
  Top Layer w20: 1700,389.01 1700,577.8
  MidLayer2 w10: v1(900,1470) 960,1470 1274,1156 1807.2,1156 1867.2,1096 v3(1867.2,1095)
  other v1: 1480,270 1870,270 1700,340 2640,410 1480,450 2640,520 2510,610 860,630 920,630 1440,670 1500,670 1870,670 1930,670 2510,670 860,690 920,690 1440,720 1500,720 1870,720 1930,720 2510,730 860,760 920,760 1440,780 1500,780 1870,780 1930,780 860,820 920,820 1440,840 1500,840 1870,840 1930,840 860,880 920,880 2510,890 2510,950 860,970 920,970 1782.2,980 2510,1010 860,1030 920,1030 1782.2,1030 2510,1070 860,1090 920,1090 1820,1100 2510,1130 860,1150 920,1150 2510,1190 860,1210 920,1210 860,1270 920,1270 860,1330 920,1330 980,1330 1040,1330 2500,1340 860,1390 920,1390 980,1390 2500,1400 2500,1460 2570,1530 2630,1530 2570,1590 2630,1590 2570,1650 2630,1650 2280,1670 2340,1670 2400,1670 2460,1670 2570,1710 2630,1710 2280,1730 2340,1730 2400,1730 2460,1730 2570,1770 2630,1770
VCC: C20.1 D5.2 R7.2 U1.16 | length 835.3
  Top Layer w12: R7.2 v3(1340,860) ; D5.2 v1(1620,1120) 1625,1120 1640,1105 1674.41,1105 U1.16
  Bottom Layer w12: v3(1340,860) 1340,890 1340,920 1540,1120 v1(1620,1120)
VCCX: C7.1 R5.1 TP3.1 U1.17 | length 884.2
  Top Layer w10: R5.1@2047.2,748.46 TP3.1@2230,748.46
  Top Layer w12: C7.1 1634.41,945.59 v1(1640,940) 1648.82,931.18 U1.17 ; v3(2040,840) 2047.2,832.8 R5.1@2047.2,748.46
  MidLayer2 w12: v1(1640,940) 1640,920 1670,890 1990,890 v3(2040,840)
pads on no net: FID1.1 FID2.1 FID3.1 H1.1 H2.1 H3.1 H4.1 L1.3

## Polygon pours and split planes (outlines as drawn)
SGND on Top Layer "Top Overlay-No Net" (solid, pour order 52): 1380,530 1380,100 1430,50 1870,50 1900,80 1900,400 1880,420 1560,420 1540,440 1540,530 1520,550 1400,550
SGND on Top Layer "Top Layer-No Net 5" (solid, pour order 57): 730,80 730,1450 760,1480 1080,1480 1130,1530 1130,2090 1200,2160 2150,2160 2220,2090 2220,1860 2270,1810 2680,1810 2740,1750 2740,80 2700,40 2340,40 2300,80 2300,860 2280,880 1125,880 1100,860 1100,80 1060,40 770,40
NetC9_1 on Top Layer "Top Layer-No Net 4" (solid, pour order 56): 2800,70 2790,1740 2680,1850 2680,2570 2710,2600 3070,2600 3100,2570 3100,2370 3250,2250 3390,2250 3450,2190 3450,420 3390,360 3170,360 3100,290 3100,70 3070,40 2830,40
NetD1_1 on Top Layer "Top Layer-No Net 3" (solid, pour order 53): 1760,2570 1790,2600 2600,2600 2640,2560 2640,1890 2600,1850 2290,1850 2260,1880 2260,2130 2210,2180 1790,2180 1760,2210
NetD4_1 on Top Layer "Top Layer-No Net 2" (solid, pour order 51): 1100,1540 1080,1520 720,1520 700,1540 700,1590 800,1690 800,2130 830,2160 1070,2160 1100,2130
NetC8_2 on Top Layer "Top Layer-No Net 1" (solid, pour order 55): 40,1660 80,1620 690,1620 770,1700 770,2130 820,2180 1620,2180 1650,2210 1650,2570 1620,2600 490,2600 430,2540 430,2420 280,2270 100,2270 40,2210
NetC1_1 on Top Layer "Multi-Layer-No Net" (solid, pour order 54): 650,40 680,70 680,1530 630,1580 80,1580 40,1540 40,460 100,400 290,400 400,300 400,70 430,40
SGND on Top Layer "Top Layer-No Net" (solid, pour order 50): 1970,655 1960,645 1855,645 1845,655 1845,675 1835,685 1530,685 1520,675 1520,655 1510,645 1415,645 1405,655 1405,855 1415,865 1515,865 1525,855 1525,815 1535,805 1835,805 1845,815 1845,855 1855,865 1960,865 1970,855
SGND on Bottom Layer "Top Overlay-No Net" (solid, pour order 67): 1380,530 1380,100 1440,50 2040,50 2080,90 2080,380 2040,420 1560,420 1540,440 1540,530 1520,550 1400,550
SGND on Bottom Layer "Bottom Layer-No Net" (solid, pour order 72): 1350,70 1310,30 780,30 730,80 730,1620 800,1690 800,2130 830,2160 2150,2160 2220,2090 2220,1860 2270,1810 2680,1810 2740,1750 2740,80 2690,30 2150,30 2110,70 2110,860 2090,880 1370,880 1350,860
NetC9_1 on Bottom Layer "Top Layer-No Net 4" (solid, pour order 71): 2800,70 2790,1740 2680,1850 2680,2570 2710,2600 3070,2600 3100,2570 3100,2370 3250,2250 3390,2250 3450,2190 3450,420 3390,360 3200,360 3100,290 3100,70 3070,40 2830,40
NetD1_1 on Bottom Layer "Top Layer-No Net 3" (solid, pour order 68): 1760,2570 1790,2600 2600,2600 2640,2560 2640,1890 2600,1850 2290,1850 2260,1880 2260,2130 2210,2180 1790,2180 1760,2210
NetC8_2 on Bottom Layer "Top Layer-No Net 1" (solid, pour order 70): 40,1660 80,1620 690,1620 770,1700 770,2130 820,2180 1620,2180 1650,2210 1650,2570 1620,2600 490,2600 430,2540 430,2420 280,2270 100,2270 40,2210
NetC1_1 on Bottom Layer "Multi-Layer-No Net" (solid, pour order 69): 650,40 680,70 680,1530 630,1580 80,1580 40,1540 40,460 100,400 250,400 400,300 400,70 430,40
SGND on Bottom Layer "Top Layer-No Net" (solid, pour order 66): 1970,655 1960,645 1855,645 1845,655 1845,675 1835,685 1530,685 1520,675 1520,655 1510,645 1415,645 1405,655 1405,855 1415,865 1515,865 1525,855 1525,815 1535,805 1835,805 1845,815 1845,855 1855,865 1960,865 1970,855
SGND on MidLayer1 "Top Overlay-No Net" (solid, pour order 59): 1380,530 1380,100 1430,50 2040,50 2080,90 2080,380 2040,420 1540,420 1540,530 1520,550 1400,550
SGND on MidLayer1 "MidLayer1-No Net" (solid, pour order 62): 3450,60 3450,2570 3420,2600 2710,2600 2680,2570 2680,1850 2640,1810 2270,1810 2220,1860 2220,2090 2150,2160 830,2160 800,2130 800,1690 690,1580 80,1580 40,1540 40,70 80,30 1310,30 1350,70 1350,860 1370,880 2090,880 2110,860 2110,70 2150,30 3420,30
NetD1_1 on MidLayer1 "Top Layer-No Net 3" (solid, pour order 60): 1760,2570 1790,2600 2600,2600 2640,2560 2640,1890 2600,1850 2290,1850 2260,1880 2260,2130 2210,2180 1790,2180 1760,2210
NetC8_2 on MidLayer1 "Top Layer-No Net 1" (solid, pour order 61): 40,1660 80,1620 690,1620 770,1700 770,2130 820,2180 1620,2180 1650,2210 1650,2570 1620,2600 490,2600 430,2540 430,2420 280,2270 100,2270 40,2210
SGND on MidLayer1 "Top Layer-No Net" (solid, pour order 58): 1970,655 1960,645 1855,645 1845,655 1845,675 1835,685 1530,685 1520,675 1520,655 1510,645 1415,645 1405,655 1405,855 1415,865 1515,865 1525,855 1525,815 1535,805 1835,805 1845,815 1845,855 1855,865 1960,865 1970,855
SGND on MidLayer2 "Top Overlay-No Net" (solid, pour order 64): 1380,530 1380,100 1430,50 2040,50 2080,90 2080,380 2040,420 1540,420 1540,530 1520,550 1400,550
SGND on MidLayer2 "MidLayer2-No Net" (solid, pour order 65): 1310,30 80,30 40,70 40,2560 80,2600 3420,2600 3450,2570 3450,60 3420,30 2150,30 2110,70 2110,860 2090,880 1370,880 1350,860 1350,70
SGND on MidLayer2 "Top Layer-No Net" (solid, pour order 63): 1970,655 1960,645 1855,645 1845,655 1845,675 1835,685 1530,685 1520,675 1520,655 1510,645 1415,645 1405,655 1405,855 1415,865 1515,865 1525,855 1525,815 1535,805 1835,805 1845,815 1845,855 1855,865 1960,865 1970,855

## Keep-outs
Keep-Out Layer:
  lines w10: -5,0 ccw(c0,0) 0,-5 ; -5,0 ccw(c0,0) 0,-5 ; -5,0 ccw(c0,0) 0,-5 ; -5,0 ccw(c0,0) 0,-5 ; -5,0 -5,2655 -5,0 ; -5,3450 cw(c0,3450) 0,3455 ; -5,3450 cw(c0,3450) 0,3455 ; -5,3450 cw(c0,3450) 0,3455 ; -5,3450 cw(c0,3450) 0,3455 ; 0,-5 3505,-5 0,-5 ; 3505,2655 3505,0 3505,2655 ; 3505,2655 0,2655 3505,2655 ; 4950,3455 cw(c4950,3450) 4955,3450 ; 4950,3455 cw(c4950,3450) 4955,3450 ; 4950,3455 cw(c4950,3450) 4955,3450 ; 4950,3455 cw(c4950,3450) 4955,3450
  text ".Layer_Name" at 577,-858.49 h60

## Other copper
Top Layer:
  pour cut-out: 1880.32,1080 1880.46,1079.86 1887.2,1085 1887.2,1105 1877.2,1115 1857.2,1115 1847.2,1105 1847.2,1085 1852.2,1080
  pour cut-out: 1837.2,985 1897.2,985 1897.2,1055 1837.2,1055
  text "TI" at 3430,1996 h50 r90
  text ".CopyrightYear" at 3430,1720 h50 r90
  text "©" at 3440,1620 h105 r90
  text ".Layer_Name" at 577,-858.49 h60
MidLayer1:
  pour cut-out: 909.86,1450.14 920,1460 920,1480 910,1490 890,1490 880,1480 880,1460 890,1450
  pour cut-out: 1877.2,1075 1887.2,1085 1887.2,1105 1877.2,1115 1857.2,1115 1847.2,1105 1847.2,1085 1857.34,1074.86
  text ".layer_Name" at 580,-860 h60
MidLayer2:
  pour cut-out: 909.86,1450.14 920,1460 920,1480 910,1490 890,1490 880,1480 880,1460 890,1450
  pour cut-out: 1867.2,1115 1847.2,1095 1847.2,1085 1857.2,1075 1877.2,1075 1887.2,1085 1887.2,1105 1877.2,1115
  text ".layer_Name" at 580,-860 h60
Bottom Layer:
  pour cut-out: 909.86,1450.14 920,1460 920,1480 910,1490 890,1490 880,1480 880,1460 890,1450
  pour cut-out: 1877.2,1075 1887.34,1084.86 1887.34,1104.86 1877.34,1114.86 1857.34,1114.86 1847.34,1104.86 1847.34,1084.86 1857.34,1074.86
  text "MADE IN U.S." at 1880,2070 h50
  text "UL94V-0" at 1760,2010 h40
  text ".Layer_Name" at 577,-858.49 h60

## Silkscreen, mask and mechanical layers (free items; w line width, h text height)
Top Overlay:
  text "SW1" at 1010,2460 h50
  text "SW2" at 2310,2440 h50
  text "PGND" at 2310,1110 h40
  text "SYNC" at 2080,1060 h40
  text "PMP10681" at 3420,810 h50 r90
  text "VCCX" at 2330,690 h40
  text "VIN+" at 450,380 h50
  text "RTN" at 870,370 h50
  text "GND" at 2440,350 h50
  text "VOUT" at 2920,350 h50
  text "EN" at 1150,170 h40
  text "AGND" at 1670,80 h40
  text "12VDC 3A" at 2585,40 h40
  text "4 - 42 VDC" at 585,35 h40
  text ".Layer_Name" at 577,-858.49 h60
Bottom Overlay:
  region: 3314.5,940 3314.5,1240 3214.5,1240 3214.5,940
  text ".PRJ_Number" at 3305,1850 h60 r90
  text ".PCB_Rev" at 3309.5,1381 h60 r90
  text "-" at 3315,1305 h60 r90
  text ".Layer_Name" at 577,-858.49 h60
Top Paste:
  text ".Layer_Name" at 577,-858.49 h60
Bottom Paste:
  text ".Layer_Name" at 577,-858.49 h60
Top Solder:
  text ".Layer_Name" at 577,-858.49 h60
  text ".Layer_Name" at 577,-858.49 h60
Bottom Solder:
  text ".Layer_Name" at 577,-858.49 h60
Drill Guide:
  text ".Layer_Name" at 577,-858.49 h60
M1 Board Outline:
  lines w5: 0,0 3505,0 3505,2655
  lines w12: 0,0 3500,0 3500,2650 0,2650 0,0
M2 Board Dimensions:
  rectangle: -0.5,-285.5 124.5,-160.5
  rectangle: 124.5,-410.5 499.5,-285.5
  lines w7: -0.5,-285.5 999.5,-285.5 ; 124.5,-410.5 124.5,-160.5 ; 249.5,-410.5 249.5,-160.5 ; 499.5,-410.5 499.5,-160.5 ; 749.5,-410.5 749.5,-160.5 ; -0.5,-410.5 999.5,-410.5 999.5,-160.5 -0.5,-160.5 -0.5,-410.5
  lines w10: -0.5,-475.5 -0.5,-455.5 ; 59.5,-485.5 -0.5,-465.5 ; 59.5,-445.5 -0.5,-465.5 ; 223.58,-465.5 -0.5,-465.5 ; 775.42,-465.5 999.5,-465.5 ; 939.5,-485.5 999.5,-465.5 ; 939.5,-445.5 999.5,-465.5 ; 999.5,-475.5 999.5,-455.5
  text "1000 (mil)" at 233.58,-501.49 h60
  text ".Layer_Name" at 577,-858.49 h60
M3 3D STEP Top:
  text ".Layer_Name" at 577,-858.49 h60
M4 3D STEP Bottom:
  text ".Layer_Name" at 577,-858.49 h60
M5 Assembly Top:
  lines w7: -292,-930.17 6308,-930.17 ; -292,-726.83 6310,-726.83 ; -292,-523.5 -292,-1133.5 3713,-1133.5 6310,-1133.5 6310,-523.5 -291.5,-523.5 -291.5,-1133.5 1284,-1133.5 ; 2173,-929 2173,-523.5 ; 3926,-1133 3926,-933 ; 4902,-930 4902,-727.17
  text "COMPONENTS MARKED 'DNP' SHOULD NOT BE POPULATED, AND MAY NOT BE IN BILL OF MATERIALS" at 1153.5,-318.5 h60
  text "ASSEMBLY VARIANT:" at 1153,-434 h60
  text ".VariantName" at 2189,-434 h60
  text "PCB VIEWED FROM TOP SIDE" at -228.5,-655.67 h60
  text "PROJECT NAME =" at 2248,-655.67 h60
  text ".PRJ_Title" at 3117.5,-655.67 h60
  text "-" at 3662,-856.49 h60
  text ".PCB_SilkRev" at 3919,-856.49 h60
  text "LAYER NAME =" at -228.5,-858.49 h60
  text "ARTWORK #    =" at 2248,-858.49 h60
  text ".prj_BasePN" at 3293.5,-858.49 h60
  text ".PCB_CopperRev" at 3729.5,-858.49 h60
  text "PLOT NAME =" at -228.5,-1064.34 h60
  text ".plot_File_Name" at 577,-1064.34 h60
  text "GENERATED    :" at 3998,-1064.34 h60
  text ".Print_Date" at 4867.5,-1064.34 h60
  text ".Print_Time" at 5596.5,-1064.34 h60
M6 Assembly Bottom:
  lines w7: -292,-726.83 6310,-726.83 ; -290,-930.17 6310,-930.17 ; 1116,-930.5 1116,-727.17 ; 2134,-1133 2134,-931 ; 3845,-929 3845,-523.5 ; 4734,-1133.5 6309.5,-1133.5 6309.5,-523.5 -292,-523.5 -292,-1133.5 2305,-1133.5 6310,-1133.5 6310,-523.5
  text "COMPONENTS MARKED 'DNP' SHOULD NOT BE POPULATED, AND MAY NOT BE IN BILL OF MATERIALS" at 6102,-318 h60
  text ".VariantName" at 5058,-434 h60
  text "ASSEMBLY VARIANT:" at 6097,-434 h60
  text ".PRJ_Title" at 2900.5,-655.67 h60
  text "PROJECT NAME =" at 3770,-655.67 h60
  text "PCB VIEWED FROM BOTTOM SIDE" at 6246.5,-655.67 h60
  text "-" at 2315,-856.49 h60
  text "NATIONAL SEMICONDUCTOR" at 1045,-858.49 h60
  text ".PCB_SilkRev" at 2084,-858.49 h60
  text ".PCB_CopperRev" at 2285,-858.49 h60
  text ".prj_BasePN" at 2724.5,-858.49 h60
  text "880" at 2908,-858.49 h60
  text "ARTWORK #    =" at 3770,-858.49 h60
  text "LAYER NAME =" at 6246.5,-858.49 h60
  text ".Print_Time" at 421.5,-1064.34 h60
  text ".Print_Date" at 1150.5,-1064.34 h60
  text "GENERATED    :" at 2020,-1064.34 h60
  text ".plot_File_Name" at 5441,-1064.34 h60
  text "PLOT NAME =" at 6246.5,-1064.34 h60
M9 Title Sheet:
  drawing of 57 lines, arcs and shapes, not listed
  text "1" at 736.34,8038 h70
  text "2" at 3232,8038 h70
  text "3" at 5721.34,8038 h70
  text "4" at 8228.01,8038 h70
  text "5" at 10727,8038 h70
  text "6" at 13232,8038 h70
  text "A" at -420,6895 h70
  text "A" at 14380,6895 h70
  text "B" at -420,4515 h70
  text "B" at 14380,4515 h70
  text "C" at -420,2140 h70
  text "C" at 14380,2140 h70
  text "PROJECT TITLE:" at 11340,279 h45
  text ".PRJ_Title" at 11390,145.67 h70
  text "DESIGNED FOR:" at 11340,-22 h45
  text ".PRJ_Customer" at 11390,-162 h70
  text "D" at -420,-230 h70
  text "D" at 14380,-230 h70
  text "FILE NAME:" at 11340,-322 h45
  text ".PCB_File_Name_No_Path" at 11390,-442 h70
  text "Texas Instruments (TI) and/or its licensors do not warrant the accuracy or completeness of this specification" at 6370.5,-603.84 h45
  text "ENGINEER:" at 11340,-612 h45
  text "LAYOUT BY:" at 12845,-612 h45
  text "or any information contained therein. TI and/or its licensors do not warrant that this design will meet" at 6325.51,-716.5 h45
  text ".PRJ_Engineer" at 11390,-766.99 h70
  text ".PCB_Layout" at 12895.5,-766.99 h70
  text "the specifications, will be suitable for your application or fit for any particular purpose, or will operate in" at 6325.51,-829.17 h45
  text ".Layer_Name" at 573.5,-856.99 h60
  text "ALTIUM DESIGNER VERSION:" at 12845,-922 h45
  text "an implementation. TI and/or its licensors do not warrant that the design is production worthy. You should" at 6325.51,-941.83 h45
  text "completely validate and test your design implementation to confirm the system functionality for your application." at 6370.5,-1054.5 h45
  text ".print_Scale" at 11390,-1055.33 h70
  text ".Application_BuildNumber" at 12895.5,-1055.33 h70
  text "1" at 736.34,-1262 h70
  text "2" at 3232,-1262 h70
  text "3" at 5721.34,-1262 h70
  text "4" at 8228.01,-1262 h70
  text "5" at 10727,-1262 h70
  text "6" at 13232,-1262 h70
M10 Fab Notes:
  drawing of 185 lines, arcs and shapes, not listed
  text "DESIGN INFORMATION" at 12383.02,5919 h60
  text "MIN. TRACK WIDTH:" at 11738.46,5739 h60
  text "8" at 12834.7,5739 h60
  text "MIL" at 12989.46,5739 h60
  text "MIN. CLEARANCE:" at 11738.46,5607 h60
  text "0.2" at 12774.7,5607 h60
  text "mm" at 12989.46,5607 h60
  text "MIN. VIA PAD SIZE:" at 11738.46,5475 h60
  text "24" at 12804.71,5475 h60
  text "MIL" at 12989.46,5475 h60
  text "0.05mm (2MIL)" at 12433.46,5333.29 h60
  text "MINIMUM ANNULAR RING" at 11409.23,5329 h60
  text "EXTERNAL" at 13141.46,5329 h60
  text "PER" at 11609.23,5211 h60
  text "IPC-D-275 CLASS 2 LEVEL C" at 11829.23,5211 h60
  text "MIL, HOLES" at 13317.46,5098.71 h60
  text "+/-" at 12925,5098 h60
  text "+/-" at 13779,5098 h60
  text "REGISTRATION TOLERANCES:" at 11409.23,5093 h60
  text "METAL" at 12609,5093 h60
  text "5" at 13185.2,5093 h60
  text "3" at 14018.2,5093 h60
  text "MIL" at 14134.46,5093 h60
  text "MATERIAL:" at 11334.46,4883.54 h60
  text "FR-4 High Tg" at 12320.9,4743.21 h60
  text "FR-408" at 11755.46,4734.64 h60
  text "X" at 12167.46,4734.64 h60
  text "OTHER" at 13243.46,4734.64 h60
  text "62 MIL (1.6mm) +/-10%" at 12075.56,4571.92 h60
  text "THICKNESS:" at 11409.23,4567.64 h60
  text "X" at 11947.4,4567.64 h60
  text "OTHER" at 13360.46,4567.64 h60
  text "TOLERANCE:" at 11409.23,4409.64 h60
  text "X" at 12248.53,4409.64 h60
  text "ANSI IPC-6012 TYPE 3 CLASS 2" at 12435.48,4409.64 h60
  text "OTHER +/-" at 12435.46,4253.64 h60
  text "BOW & TWIST:" at 11409.23,4096.64 h60
  text "X" at 12248.53,4096.64 h60
  text "ANSI IPC-6012 TYPE 3 CLASS 2" at 12435.48,4096.64 h60
  text "OTHER +/-" at 12435.46,3938.13 h60
  text "DRILLING:" at 11334.46,3799.64 h60
  text "REFERENCE:" at 11409.23,3682.64 h60
  text "X" at 12057.46,3682.64 h60
  text "AS SHOWN" at 12244.46,3682.64 h60
  text "X" at 12958.46,3682.64 h60
  text "NC_DRILL FILES" at 13095.46,3682.64 h60
  text "PTH MIN COPPER THICKNESS:" at 11409.23,3524.64 h60
  text "X" at 12759.46,3524.64 h60
  text "1MIL" at 12896.46,3524.64 h60
  text "OTHER" at 13393.46,3524.64 h60
  text "BOARD FINISH:" at 11334.46,3365.64 h60
  text "SILKSCREEN:" at 11489.68,3247.64 h60
  text "X" at 12438.46,3247.64 h60
  text "TOP" at 12564.46,3247.64 h60
  text "X" at 12948.46,3247.64 h60
  text "BOTTOM" at 13075.46,3247.64 h60
  text "SILKSCREEN COLOR:" at 11489.68,3080.64 h60
  text "X" at 12437.42,3080.64 h60
  text "WHITE" at 12564.46,3080.64 h60
  text "OTHER" at 13075.46,3080.64 h60
  text "SOLDER RESIST COLOR:" at 11489.68,2910.64 h60
  text "X" at 12057.42,2751.44 h60
  text "GREEN" at 12184.46,2751.44 h60
  text "BLUE" at 12775.46,2751.44 h60
  text "OTHER" at 13313.46,2751.44 h60
  text "IMMERSION GOLD (ENIG)" at 12395.46,2562.92 h60
  text "ENEPIG" at 13733,2559.64 h60
  text "SURFACE FINISH:" at 11334.46,2558.64 h60
  text "X" at 12208.51,2558.64 h60
  text "IMM. TIN/SILVER OR EQUIV" at 11664,2401.64 h60
  text "OTHER" at 13095.46,2401.64 h60
  text "ARRAY/PANEL:" at 11334.46,2222.64 h60
  text "CUT AND TRIM PER MECH LAYER 1" at 12395.46,2218.35 h60
  text "N.C. ROUTE" at 12395.46,2066.64 h60
  text "X" at 13074.46,2066.64 h60
  text "V. SCORE" at 13261.46,2066.64 h60
  text "CERTIFICATION:" at 11334.46,1929.64 h60
  text "MATERIALS AND WORKMANSHIP FOR ALL PCBS" at 12059.46,1929.64 h60
  text "TO MEET OR EXCEED THE REQUIREMENTS OF:" at 12059.46,1831.64 h60
  text "X" at 11685.96,1695.13 h60
  text "ANSI IPC-A-600F CLASS ->" at 11824.96,1695.13 h60
  text "X" at 13464.02,1695.13 h60
  text "2" at 13582.96,1695.14 h60
  text "1" at 13267.96,1693.64 h60
  text "3" at 13936.96,1693.64 h60
  text "X" at 11688.02,1535.64 h60
  text "UL 94V-0" at 11824.96,1535.64 h60
  text "X" at 12500.02,1535.64 h60
  text "RoHS" at 12636.96,1535.64 h60
  text "OTHER" at 13281.36,1535.64 h60
  text "PER ORDER" at 13678.42,1535.64 h60
  text "ADDITIONAL REQUIREMENTS:" at 11334.46,1394.64 h60
  text "MICROSECTION:" at 11409.23,1279.64 h60
  text "YES" at 12314.96,1279.64 h60
  text "REQUIRED" at 13176.46,1123.49 h60
  text "BARE BOARD ELEC. TEST:" at 11409.23,1120.64 h60
  text "NONE" at 12714.96,1120.64 h60
  text "X" at 13049.46,1120.64 h60
  text "PER ORDER" at 13768.46,1120.64 h60
  text "X" at 12950,965 h60
  text "MANUFACTURER'S UL:" at 11409.23,963.64 h60
  text "RAIL" at 12574.96,959.35 h60
  text "METAL" at 13066.77,959.35 h60
  text "SILK" at 13578.46,959.35 h60
  text ".Layer_Name" at 577,-858.49 h60
M11 Gerber Information:
  lines w10: -292,-931.67 6308,-931.67 ; -292,-728.33 6310,-728.33 ; -292,-525 -292,-1135 3713,-1135 6310,-1135 6310,-525 -291.5,-525 -291.5,-1135 1284,-1135 ; 2173,-1135 2173,-525 ; 3440,-728.33 3440,-525 ; 4280,-728.33 4280,-525 ; 4902,-1141.5 4902,-938.67
  text "ALL ARTWORK VIEWED FROM TOP SIDE" at -228.5,-657.17 h60
  text "BOARD #:" at 2248,-657.17 h60
  text ".PRJ_Number" at 2793.5,-657.17 h60
  text "REV:" at 3638,-657.17 h60
  text ".PCB_Rev" at 3929.5,-657.17 h60
  text "SVN REV:" at 4476,-657.17 h60
  text ".VersionControl_RevNumber" at 4982,-657.17 h60
  text "LAYER NAME =" at -228.5,-859.99 h60
  text "TID #:" at 2248,-860.5 h60
  text ".TID" at 2793.5,-860.5 h60
  text "PLOT NAME =" at -228.5,-1065.84 h60
  text ".plot_File_Name" at 577,-1065.84 h60
  text "GENERATED    :" at 2250,-1065.84 h60
  text ".Print_Date" at 3119.5,-1065.84 h60
  text ".Print_Time" at 3848.5,-1065.84 h60
  text "TEXAS INSTRUMENTS" at 5113,-1065.84 h60
M12 Stackup:
  drawing of 295 lines, arcs and shapes, not listed
  text "Layer" at 9805,7855 h60
  text "Name" at 10214.91,7855 h60
  text "Material" at 11144.66,7855 h60
  text "Thickness" at 12004.42,7855 h60
  text "Constant" at 12654.26,7855 h60
  text "Board Layer Stack" at 13224.12,7855 h60
  text "1" at 9805,7735 h60
  text "Top Overlay" at 10214.91,7735 h60
  text "2" at 9805,7615 h60
  text "Top Solder" at 10214.91,7615 h60
  text "Solder Resist" at 11144.66,7615 h60
  text "0.40mil" at 12004.42,7615 h60
  text "3.5" at 12654.26,7615 h60
  text "3" at 9805,7495 h60
  text "Top Layer" at 10214.91,7495 h60
  text "Copper" at 11144.66,7495 h60
  text "2.80mil" at 12004.42,7495 h60
  text "4" at 9805,7375 h60
  text "Dielectric1" at 10214.91,7375 h60
  text "FR-4" at 11144.66,7375 h60
  text "17.00mil" at 12004.42,7375 h60
  text "4.8" at 12654.26,7375 h60
  text "5" at 9805,7255 h60
  text "MidLayer1" at 10214.91,7255 h60
  text "Copper" at 11144.66,7255 h60
  text "2.80mil" at 12004.42,7255 h60
  text "6" at 9805,7135 h60
  text "Dielectric2" at 10214.91,7135 h60
  text "FR-4" at 11144.66,7135 h60
  text "17.00mil" at 12004.42,7135 h60
  text "4.8" at 12654.26,7135 h60
  text "7" at 9805,7015 h60
  text "MidLayer2" at 10214.91,7015 h60
  text "Copper" at 11144.66,7015 h60
  text "2.80mil" at 12004.42,7015 h60
  text "8" at 9805,6895 h60
  text "Dielectric3" at 10214.91,6895 h60
  text "FR-4" at 11144.66,6895 h60
  text "17.00mil" at 12004.42,6895 h60
  text "4.8" at 12654.26,6895 h60
  text "9" at 9805,6775 h60
  text "Bottom Layer" at 10214.91,6775 h60
  text "Copper" at 11144.66,6775 h60
  text "2.80mil" at 12004.42,6775 h60
  text "10" at 9805,6655 h60
  text "Bottom Solder" at 10214.91,6655 h60
  text "Solder Resist" at 11144.66,6655 h60
  text "0.40mil" at 12004.42,6655 h60
  text "3.5" at 12654.26,6655 h60
  text "11" at 9805,6535 h60
  text "Bottom Overlay" at 10214.91,6535 h60
  text ".layer_Name" at 580,-870 h60
M13 Component Bodies Top:
  text ".Layer_Name" at 577,-858.49 h60
M14 Component Bodies Bottom:
  text ".Layer_Name" at 577,-858.49 h60
M15 Courtyards Top:
  text ".Layer_Name" at 577,-858.49 h60
M16 Courtyards Bottom:
  text ".Layer_Name" at 577,-858.49 h60
Drill Drawing:
  circle w10: c5692.72,2371.72 r24.89
  lines w10: 5667.83,1762 5680.27,1762 5680.27,1749.56 5705.16,1749.56 5705.16,1762 5717.6,1762 5717.6,1786.89 5705.16,1786.89 5705.16,1799.33 5680.27,1799.33 5680.27,1786.89 5667.83,1786.89 5667.83,1762 ; 5667.83,1898.88 5692.72,1911.32 5717.6,1898.88 5705.16,1923.76 5717.6,1948.65 5692.72,1936.21 5667.83,1948.65 5680.27,1923.76 5667.83,1898.88 ; 5667.83,2060.64 5680.27,2060.64 5692.72,2048.2 5705.16,2060.64 5717.6,2060.64 5705.16,2073.08 5717.6,2085.53 5705.16,2085.53 5692.72,2097.97 5680.27,2085.53 5667.83,2085.53 5680.27,2073.08 5667.83,2060.64 ; 5667.83,2247.29 5717.6,2247.29 5692.72,2197.52 5667.83,2247.29 ; 5667.83,2496.16 5717.6,2496.16 5717.6,2545.93 5667.83,2545.93 5667.83,2496.16
  lines w12: 5600,1704.76 7718.02,1704.76 ; 5600,2600.68 7718.02,2600.68 ; 5970.36,1555.44 5970.36,2750 ; 6327.36,1555.44 6327.36,2750 ; 6988.93,1555.44 6988.93,2750 ; 7273.07,1555.44 7273.07,2750 ; 5600,1555.44 7718.02,1555.44 7718.02,2750 5600,2750 5600,1555.44
  text "Symbol" at 5689.59,2645.48 h72
  text "Quantity" at 6015.16,2645.48 h72
  text "Finished Hole Size" at 6372.16,2645.48 h72
  text "Plated" at 7033.72,2645.48 h72
  text "Hole Type" at 7317.86,2645.48 h72
  text "24" at 6015.16,2496.16 h60
  text "8.00mil (0.203mm)" at 6372.16,2496.16 h60
  text "PTH" at 7033.72,2496.16 h60
  text "Round" at 7317.86,2496.16 h60
  text "193" at 6015.16,2346.84 h60
  text "10.00mil (0.254mm)" at 6372.16,2346.84 h60
  text "PTH" at 7033.72,2346.84 h60
  text "Round" at 7317.86,2346.84 h60
  text "2" at 6015.16,2197.52 h60
  text "14.00mil (0.356mm)" at 6372.16,2197.52 h60
  text "PTH" at 7033.72,2197.52 h60
  text "Round" at 7317.86,2197.52 h60
  text "7" at 6015.16,2048.2 h60
  text "63.00mil (1.600mm)" at 6372.16,2048.2 h60
  text "PTH" at 7033.72,2048.2 h60
  text "Round" at 7317.86,2048.2 h60
  text "4" at 6015.16,1898.88 h60
  text "122.05mil (3.100mm)" at 6372.16,1898.88 h60
  text "PTH" at 7033.72,1898.88 h60
  text "Round" at 7317.86,1898.88 h60
  text "4" at 6015.16,1749.56 h60
  text "125.98mil (3.200mm)" at 6372.16,1749.56 h60
  text "PTH" at 7033.72,1749.56 h60
  text "Round" at 7317.86,1749.56 h60
  text "234 Total" at 6015.16,1600.24 h60
  text ".Layer_Name" at 577,-858.49 h60

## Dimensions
0,0 to 0,2650 on M2 Board Dimensions
0,0 to 3500,0 on M2 Board Dimensions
